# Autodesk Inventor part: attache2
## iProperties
Created: 2002-09
Part Number: attache2
Material: Par défaut
Document SubType Name: Modélisation
Designer: fmarro
Control State: 0
Master: False
Checked Out: False
Shininess: 70.0
Length Units: 11269
Angle Units: 11279
Time Units: 11290
Mass Units: 11283
Length Display Precision: 3
Angle Display Precision: 2
Density: 0.0
Volumn: 0.0
Area: 0.0
PropertySet Name: Model Information
Author: fmarro
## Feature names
1. Extrusion1
2. Extrusion3
3. Symétrie1 [Mirror]
4. Congé1 [Fillet]
5. Congé2 [Fillet]
6. Extrusion4
